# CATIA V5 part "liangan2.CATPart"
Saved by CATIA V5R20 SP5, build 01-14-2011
Part number: 连杆2
Bounding box of the stored display mesh (mm): x -20 to 170, y -20 to 20, z 0 to 40
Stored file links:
  E:\scc\liangan\新建文件夹\liangan2.CATPart
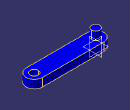
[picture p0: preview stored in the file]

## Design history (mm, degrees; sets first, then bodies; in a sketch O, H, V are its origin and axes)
Body1 (main body)
  Sketch1 on xy-plane, origin (0, 0, 0), H (1, 0, 0), V (0, 1, 0)
    construction line L1 (0, 0) -> (150, 0)
    line L2 (0, 20) -> (150, 20)
    line L3 (150, -20) -> (0, -20)
    arc A1 centre (150, 0) radius 20 from (150, 20) to (150, -20) cw
    arc A2 centre (0, 0) radius 20 from (0, -20) to (0, 20) cw
    circle A3 centre (150, 0) radius 10
    distance L1 L2 = 20
    radius A3 = 10
    horizontal: L1 H
    tangency: A1 L2, A2 L2, A1 L3, A2 L3
  Pad1: profile Sketch1, direction (0, 0, 1), length 20
  Sketch2 on end face of Pad1, origin (0, 0, 20), H (1, 0, 0), V (0, 1, 0)
    circle A1 centre (0, 0) radius 10
    radius A1 = 10
  Pad2: profile Sketch2, direction (0, 0, 1), length 20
